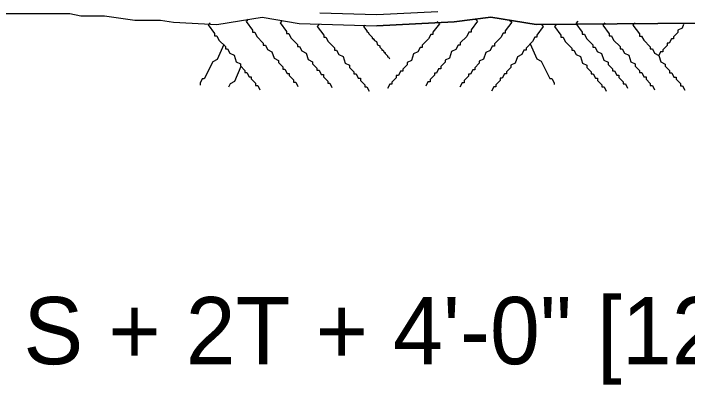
# Model space of a CAD drawing. Extents: x 49991.4 to 50021, y 49987.6 to 50011.4.
# Drawn here: x 50012.479 to 50013.08, y 50000.897 to 50001.228 of the extents above; entities that cross this region are included whole.
import ezdxf

# ---------------------------------------------------------------- set-up
doc = ezdxf.new("R2010")
doc.units = 0
doc.layers.add('Level 1', color=7, linetype='Continuous')
doc.layers.add('Level 2', color=7, linetype='Continuous')

msp = doc.modelspace()

# ---------------------------------------------------------------- linework, layer by layer
at = {"layer": 'Level 1'}
for points in [[(50012.45381, 50001.22772), (50012.48466, 50001.22772), (50012.52897, 50001.22772), (50012.53865, 50001.22576), (50012.55984, 50001.22576), (50012.58686, 50001.22194), (50012.60995, 50001.22194), (50012.62151, 50001.22), (50012.66009, 50001.21804), (50012.70054, 50001.22456), (50012.73373, 50001.21877), (50012.80309, 50001.21679)], [(50012.75199, 50001.22825), (50012.79249, 50001.2271), (50012.80298, 50001.2268), (50012.85756, 50001.22957)], [(50012.68819, 50001.22257), (50012.68623, 50001.22063), (50012.69206, 50001.21291), (50012.69206, 50001.21099), (50012.69396, 50001.21099), (50012.69588, 50001.20712), (50012.70166, 50001.20136), (50012.70166, 50001.1994), (50012.7036, 50001.1994), (50012.70552, 50001.19554), (50012.70938, 50001.19364), (50012.71132, 50001.18782), (50012.71514, 50001.18592), (50012.71514, 50001.184), (50012.719, 50001.1801), (50012.719, 50001.17822), (50012.72096, 50001.17822), (50012.72286, 50001.17436), (50012.72482, 50001.17436), (50012.72482, 50001.17242), (50012.72865, 50001.16855), (50012.72865, 50001.16663), (50012.73057, 50001.16663), (50012.73255, 50001.16277)], [(50012.71865, 50001.2214), (50012.71671, 50001.21948), (50012.72251, 50001.21176), (50012.72251, 50001.20984), (50012.72444, 50001.20984), (50012.72638, 50001.20598), (50012.73216, 50001.20021), (50012.73216, 50001.19825), (50012.7341, 50001.19825), (50012.73602, 50001.19443), (50012.73988, 50001.19251), (50012.74178, 50001.18667), (50012.74564, 50001.18477), (50012.74564, 50001.18285), (50012.74948, 50001.17899), (50012.74948, 50001.17707), (50012.75146, 50001.17707), (50012.75334, 50001.17321), (50012.75532, 50001.17321), (50012.75532, 50001.17127), (50012.75914, 50001.16744), (50012.75914, 50001.16548), (50012.76107, 50001.16548), (50012.76297, 50001.16162)], [(50012.80309, 50001.21679), (50012.8721, 50001.22029), (50012.90495, 50001.22456), (50012.9454, 50001.21804), (50013.19865, 50001.22)], [(50013.19865, 50001.22), (50012.9454, 50001.21804), (50012.90495, 50001.22456), (50012.8721, 50001.22029), (50012.80309, 50001.21679)], [(50012.85704, 50001.22065), (50012.85896, 50001.21867), (50012.85318, 50001.21097), (50012.85318, 50001.20903), (50012.85127, 50001.20903), (50012.84931, 50001.2052), (50012.84351, 50001.19938), (50012.84351, 50001.19748), (50012.84159, 50001.19748), (50012.83969, 50001.19362), (50012.83585, 50001.19166), (50012.83391, 50001.1859), (50012.83001, 50001.18394), (50012.83001, 50001.18206), (50012.82619, 50001.1782), (50012.82619, 50001.17626), (50012.82425, 50001.17626), (50012.82233, 50001.1724), (50012.82041, 50001.1724), (50012.82041, 50001.17048), (50012.81655, 50001.16661), (50012.81655, 50001.16471), (50012.81461, 50001.16471), (50012.81268, 50001.16081)], [(50012.89106, 50001.22275), (50012.893, 50001.22083), (50012.8872, 50001.21311), (50012.8872, 50001.21119), (50012.88528, 50001.21119), (50012.88334, 50001.20733), (50012.87755, 50001.20157), (50012.87755, 50001.19961), (50012.87561, 50001.19961), (50012.87369, 50001.19579), (50012.86983, 50001.19387), (50012.86793, 50001.18803), (50012.86407, 50001.18612), (50012.86407, 50001.1842), (50012.86023, 50001.18034), (50012.86023, 50001.17842), (50012.85825, 50001.17842), (50012.85637, 50001.17456), (50012.85439, 50001.17456), (50012.85439, 50001.17262), (50012.85057, 50001.1688), (50012.85057, 50001.16684), (50012.84865, 50001.16684), (50012.84675, 50001.16298)], [(50012.92148, 50001.22189), (50012.92344, 50001.21995), (50012.91762, 50001.21223), (50012.91762, 50001.21031), (50012.91572, 50001.21031), (50012.9138, 50001.20645), (50012.90802, 50001.20069), (50012.90802, 50001.19873), (50012.90608, 50001.19873), (50012.90416, 50001.19487), (50012.9003, 50001.19297), (50012.89836, 50001.18714), (50012.89454, 50001.18524), (50012.89454, 50001.18332), (50012.89067, 50001.17942), (50012.89067, 50001.17754), (50012.88871, 50001.17754), (50012.88681, 50001.17368), (50012.88485, 50001.17368), (50012.88485, 50001.17174), (50012.88103, 50001.16788), (50012.88103, 50001.16596), (50012.87911, 50001.16596), (50012.87713, 50001.1621)], [(50012.98259, 50001.22092), (50012.98063, 50001.21898), (50012.98645, 50001.21125), (50012.98645, 50001.20933), (50012.98835, 50001.20933), (50012.99027, 50001.20547), (50012.99605, 50001.19971), (50012.99605, 50001.19775), (50012.99799, 50001.19775), (50012.99991, 50001.19389), (50013.00378, 50001.19199), (50013.00572, 50001.18617), (50013.00954, 50001.18427), (50013.00954, 50001.18235), (50013.0134, 50001.17844), (50013.0134, 50001.17656), (50013.01536, 50001.17656), (50013.01726, 50001.1727), (50013.01922, 50001.1727), (50013.01922, 50001.17076), (50013.02304, 50001.1669), (50013.02304, 50001.16498), (50013.02496, 50001.16498), (50013.02694, 50001.16112)], [(50012.6543, 50001.21952), (50012.6524, 50001.21758), (50012.65816, 50001.2099), (50012.65816, 50001.20792), (50012.66009, 50001.20792), (50012.66203, 50001.20408), (50012.66777, 50001.19832), (50012.66777, 50001.19636), (50012.66973, 50001.19636), (50012.67167, 50001.1925), (50012.67553, 50001.19056), (50012.67745, 50001.18477), (50012.68127, 50001.18289), (50012.68127, 50001.18095), (50012.68517, 50001.17705), (50012.68517, 50001.17515), (50012.68707, 50001.17515), (50012.68903, 50001.17131), (50012.69093, 50001.17131), (50012.69093, 50001.16937), (50012.69479, 50001.16551), (50012.69479, 50001.16359), (50012.69672, 50001.16359), (50012.69864, 50001.15973)], [(50012.75172, 50001.21827), (50012.7498, 50001.21629), (50012.75558, 50001.20858), (50012.75558, 50001.20664), (50012.75748, 50001.20664), (50012.75944, 50001.20282), (50012.76524, 50001.197), (50012.76524, 50001.1951), (50012.76716, 50001.1951), (50012.76906, 50001.19124), (50012.7729, 50001.18928), (50012.77485, 50001.18352), (50012.77875, 50001.18156), (50012.77875, 50001.17968), (50012.78257, 50001.17581), (50012.78257, 50001.17387), (50012.78451, 50001.17387), (50012.78643, 50001.17001), (50012.78835, 50001.17001), (50012.78835, 50001.16809), (50012.79221, 50001.16423), (50012.79221, 50001.16233), (50012.79415, 50001.16233), (50012.79607, 50001.15843)], [(50012.79221, 50001.2171), (50012.79126, 50001.21613), (50012.79413, 50001.21231), (50012.79413, 50001.21132), (50012.79512, 50001.21132), (50012.79607, 50001.2094), (50012.79898, 50001.20651), (50012.79898, 50001.20554), (50012.79991, 50001.20554), (50012.8009, 50001.20364), (50012.8028, 50001.20265), (50012.80377, 50001.19978), (50012.80571, 50001.19881), (50012.80571, 50001.19782), (50012.80765, 50001.19591), (50012.80765, 50001.19494), (50012.80862, 50001.19494), (50012.80957, 50001.193), (50012.81056, 50001.193), (50012.81056, 50001.19205), (50012.81248, 50001.19013), (50012.81248, 50001.18914), (50012.81344, 50001.18914), (50012.81439, 50001.18722)], [(50012.94981, 50001.21817), (50012.95171, 50001.21623), (50012.94595, 50001.20855), (50012.94595, 50001.20657), (50012.94403, 50001.20657), (50012.94209, 50001.20273), (50012.93635, 50001.19697), (50012.93635, 50001.19501), (50012.93439, 50001.19501), (50012.93244, 50001.19115), (50012.92858, 50001.18921), (50012.92666, 50001.18342), (50012.92284, 50001.18154), (50012.92284, 50001.1796), (50012.91894, 50001.1757), (50012.91894, 50001.1738), (50012.91704, 50001.1738), (50012.91508, 50001.16996), (50012.91318, 50001.16996), (50012.91318, 50001.16802), (50012.90932, 50001.16416), (50012.90932, 50001.16224), (50012.9074, 50001.16224), (50012.90548, 50001.15838)], [(50012.96358, 50001.21818), (50012.96162, 50001.21624), (50012.96744, 50001.20852), (50012.96744, 50001.2066), (50012.96934, 50001.2066), (50012.97126, 50001.20273), (50012.97704, 50001.19697), (50012.97704, 50001.19501), (50012.97898, 50001.19501), (50012.9809, 50001.19115), (50012.98476, 50001.18925), (50012.9867, 50001.18343), (50012.99052, 50001.18153), (50012.99052, 50001.17961), (50012.99439, 50001.17571), (50012.99439, 50001.17383), (50012.99635, 50001.17383), (50012.99825, 50001.16997), (50013.00021, 50001.16997), (50013.00021, 50001.16802), (50013.00403, 50001.16416), (50013.00403, 50001.16224), (50013.00595, 50001.16224), (50013.00793, 50001.15838)], [(50013.00675, 50001.21937), (50013.00481, 50001.21745), (50013.01061, 50001.20973), (50013.01061, 50001.20781), (50013.01253, 50001.20781), (50013.01447, 50001.20395), (50013.02025, 50001.19818), (50013.02025, 50001.19622), (50013.02219, 50001.19622), (50013.02411, 50001.1924), (50013.02797, 50001.19048), (50013.02987, 50001.18464), (50013.03374, 50001.18274), (50013.03374, 50001.18082), (50013.03758, 50001.17696), (50013.03758, 50001.17504), (50013.03956, 50001.17504), (50013.04144, 50001.17118), (50013.04342, 50001.17118), (50013.04342, 50001.16924), (50013.04724, 50001.16542), (50013.04724, 50001.16346), (50013.04916, 50001.16346), (50013.05106, 50001.15959)], [(50013.03362, 50001.21928), (50013.0317, 50001.2173), (50013.03748, 50001.2096), (50013.03748, 50001.20766), (50013.03938, 50001.20766), (50013.04134, 50001.20384), (50013.04714, 50001.19802), (50013.04714, 50001.19612), (50013.04906, 50001.19612), (50013.05096, 50001.19225), (50013.0548, 50001.19029), (50013.05674, 50001.18453), (50013.06065, 50001.18257), (50013.06065, 50001.18069), (50013.06447, 50001.17683), (50013.06447, 50001.17489), (50013.06641, 50001.17489), (50013.06833, 50001.17103), (50013.07025, 50001.17103), (50013.07025, 50001.16911), (50013.07411, 50001.16525), (50013.07411, 50001.16335), (50013.07605, 50001.16335), (50013.07797, 50001.15945)], [(50013.0768, 50001.218), (50013.07575, 50001.21477), (50013.07185, 50001.21285), (50013.07185, 50001.21093), (50013.06802, 50001.20707), (50013.06802, 50001.20513), (50013.0661, 50001.20513), (50013.06412, 50001.20131), (50013.06222, 50001.20131), (50013.06222, 50001.19935), (50013.05838, 50001.19548), (50013.05838, 50001.19358), (50013.05644, 50001.19358), (50013.05452, 50001.18972)], [(50012.66636, 50001.20022), (50012.66054, 50001.18673), (50012.65672, 50001.18477), (50012.64896, 50001.16937), (50012.64706, 50001.16937), (50012.64514, 50001.16551), (50012.64514, 50001.16386)], [(50012.94004, 50001.20068), (50012.94586, 50001.18719), (50012.94969, 50001.18523), (50012.95745, 50001.16983), (50012.95935, 50001.16983), (50012.96127, 50001.16597), (50012.96127, 50001.16433)], [(50012.68164, 50001.18058), (50012.67586, 50001.16706), (50012.67196, 50001.16514), (50012.67045, 50001.16207)]]:
    msp.add_lwpolyline(points, dxfattribs=at)

# ---------------------------------------------------------------- texts
at = {"layer": 'Level 2'}
msp.add_text('S + 2T + 4\'-0" [1200]', height=0.06, dxfattribs=at).set_placement((50012.48738, 50000.91482))

doc.saveas('drawing.dxf')
